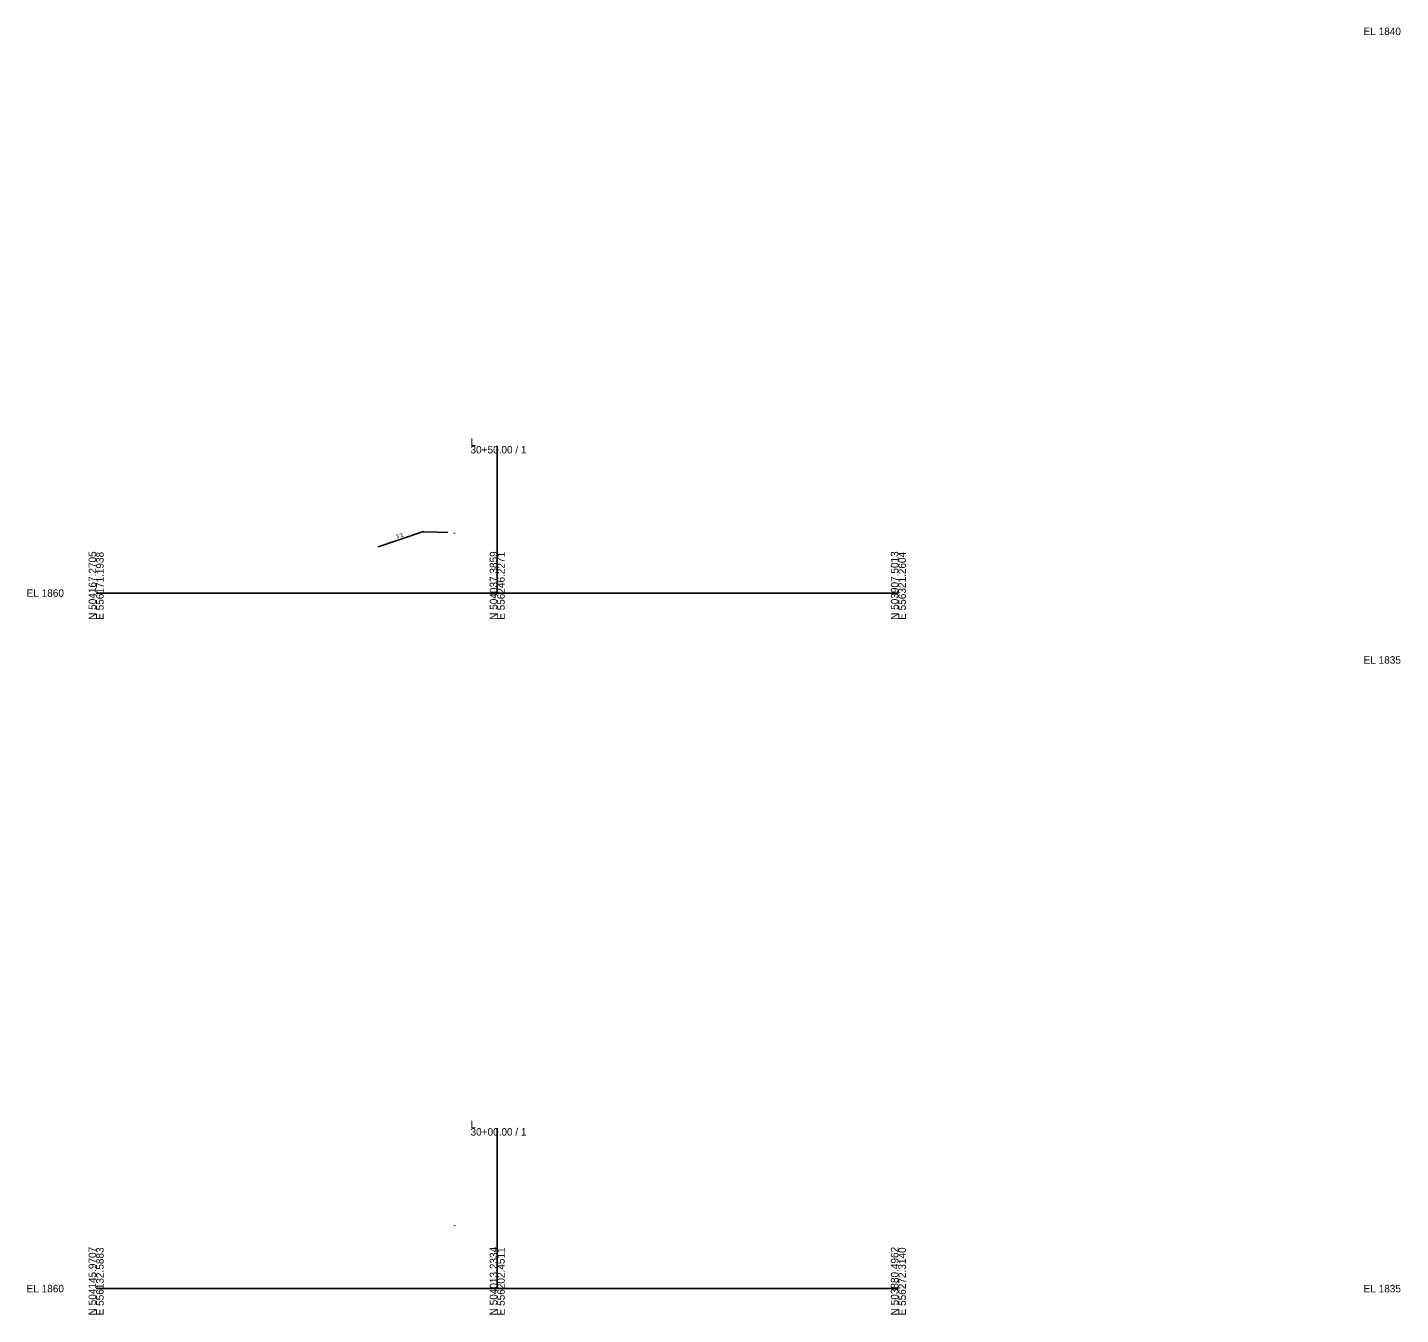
# Model space of a CAD drawing. Extents: x -26 to 3303, y -10 to 4703.
# Drawn here: x 974 to 1488, y -10 to 471 of the extents above; entities that cross this region are included whole.
import ezdxf

# ---------------------------------------------------------------- set-up
doc = ezdxf.new("R2010")
doc.units = 0
for name, color, linetype in [('Exist Cross Section Cell', 7, 'Continuous'), ('Scratch_Level_0', 7, 'Continuous'), ('Scratch_Level_9', 7, 'Continuous')]:
    doc.layers.add(name, color=color, linetype=linetype)

msp = doc.modelspace()

# ---------------------------------------------------------------- linework, layer by layer
at = {"layer": 'Exist Cross Section Cell'}
for p, q in [((1150, 260), (1150, 315)), ((1000, 260), (1150, 260)), ((1150, 260), (1300, 260)), ((1150, 0), (1150, 60)), ((1000, 0), (1150, 0)), ((1150, 0), (1300, 0))]:
    msp.add_line(p, q, dxfattribs=at)
at = {"layer": 'Scratch_Level_0'}
msp.add_line((1122.5, 282.84), (1127.5, 282.74), dxfattribs=at)
for points in [[(1105.41, 277.32), (1105.41, 277.32), (1122, 282.85)], [(1122, 282.85), (1122.5, 282.84), (1122.5, 282.84)], [(1127.5, 282.74), (1131.5, 282.66), (1131.5, 282.66)]]:
    msp.add_lwpolyline(points, dxfattribs=at)
at = {"layer": 'Scratch_Level_9'}
for points in [[(1134, 282.56), (1134, 282.31)], [(1134, 23.76), (1134, 23.51)]]:
    msp.add_lwpolyline(points, dxfattribs=at)

# ---------------------------------------------------------------- texts
at = {"layer": 'Exist Cross Section Cell'}
for s, p in [('EL 1840', (1474, 468.6)), ('30+50.00 / 1', (1140, 312.2)), ('L', (1140, 315)), ('EL 1860', (974, 258.6)), ('EL 1835', (1474, 233.6)), ('L', (1140, 60)), ('30+00.00 / 1', (1140, 57.2)), ('EL 1860', (974, -1.4)), ('EL 1835', (1474, -1.4))]:
    msp.add_text(s, height=2.8, dxfattribs=at).set_placement(p)
for s, p in [('N 504167.2705', (1000, 250)), ('E 556171.1938', (1002.8, 250)), ('N 504037.3859', (1150, 250)), ('E 556246.2271', (1152.8, 250)), ('N 503907.5013', (1300, 250)), ('E 556321.2604', (1302.8, 250)), ('N 504145.9707', (1000, -10)), ('N 504013.2334', (1150, -10)), ('N 503880.4962', (1300, -10)), ('E 556132.5883', (1002.8, -10)), ('E 556202.4511', (1152.8, -10)), ('E 556272.3140', (1302.8, -10))]:
    msp.add_text(s, height=2.8, rotation=90, dxfattribs=at).set_placement(p)
at = {"layer": 'Scratch_Level_0'}
msp.add_text('3:1', height=1.5, rotation=18.4332, dxfattribs=at).set_placement((1112.32, 280.36))
for p in [(1122, 282.85), (1122.5, 282.84), (1127.5, 282.74)]:
    msp.add_text('X', height=0.0025, dxfattribs=at).set_placement(p)

doc.saveas('drawing.dxf')
